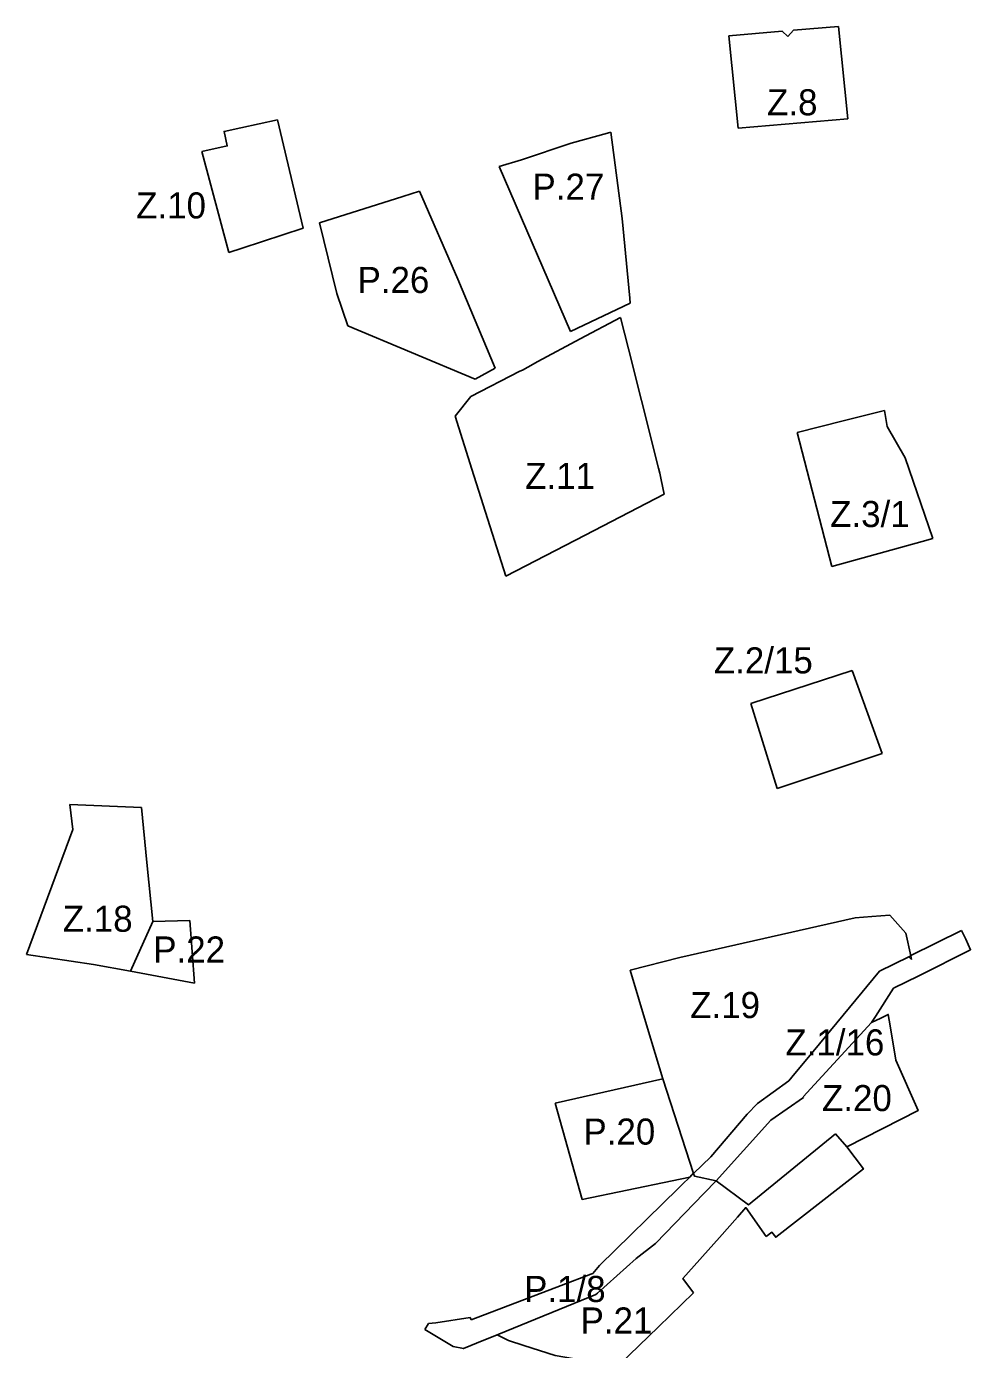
# Model space of a CAD drawing. Extents: x -438701 to -435614, y -1126017 to -1121766.
# Drawn here: x -438217 to -437855, y -1124104 to -1123597 of the extents above; entities that cross this region are included whole.
import ezdxf

# ---------------------------------------------------------------- set-up
doc = ezdxf.new("R2010")
doc.units = 0
for name, color, linetype in [('NAVRH', 7, 'Continuous'), ('STAV', 7, 'Continuous'), ('Vrstva 3', 7, 'Continuous'), ('Vrstva 6', 7, 'Continuous'), ('Vrstva 7', 7, 'Continuous'), ('Vrstva 9', 7, 'Continuous')]:
    doc.layers.add(name, color=color, linetype=linetype)

msp = doc.modelspace()

# ---------------------------------------------------------------- linework, layer by layer
at = {"layer": 'NAVRH'}
for p, q in [((-437905.63, -1123597.23), (-437922.91, -1123598.68)), ((-437902.09, -1123632.64), (-437905.63, -1123597.23)), ((-437927.28, -1123599.05), (-437947.65, -1123600.76)), ((-437947.65, -1123600.76), (-437944.07, -1123636.19)), ((-437925.07, -1123601.06), (-437927.28, -1123599.05)), ((-437922.91, -1123598.68), (-437925.07, -1123601.06)), ((-438110.79, -1123674.54), (-438120.57, -1123632.97)), ((-437944.07, -1123636.19), (-437902.09, -1123632.64)), ((-438149.56, -1123645.16), (-438139.27, -1123683.83)), ((-438024.67, -1123727.86), (-438026.73, -1123728.92)), ((-438020.8, -1123725.67), (-438024.67, -1123727.86)), ((-438046.51, -1123739.05), (-438052.5, -1123746.58)), ((-437887.06, -1123750.53), (-437888.12, -1123744.39)), ((-438052.5, -1123746.58), (-438046.07, -1123766.9)), ((-437921.51, -1123752.84), (-437908.29, -1123804.25)), ((-437880.1, -1123762.54), (-437887.06, -1123750.53)), ((-437869.51, -1123793.43), (-437880.1, -1123762.54)), ((-438046.07, -1123766.9), (-438033.09, -1123807.96)), ((-438002.75, -1123792.21), (-437972.43, -1123776.46)), ((-438033.09, -1123807.96), (-438002.75, -1123792.21)), ((-437908.29, -1123804.25), (-437873.67, -1123794.59)), ((-437873.67, -1123794.59), (-437869.51, -1123793.43)), ((-437900.38, -1123844.04), (-437939.31, -1123856.78)), ((-437889, -1123875.95), (-437900.38, -1123844.04)), ((-437939.31, -1123856.78), (-437929.11, -1123889.32)), ((-437929.11, -1123889.32), (-437889, -1123875.95)), ((-438170.63, -1123917.63), (-438172.73, -1123896.63)), ((-438168.37, -1123940.3), (-438170.63, -1123917.63)), ((-438176.87, -1123959.38), (-438168.37, -1123940.3)), ((-437856.96, -1123947.06), (-437858.53, -1123943.79)), ((-438216.73, -1123952.89), (-438191.04, -1123956.73)), ((-438191.04, -1123956.73), (-438176.87, -1123959.38)), ((-437889.94, -1123959.3), (-437878.74, -1123953.77)), ((-437878.74, -1123953.77), (-437889.94, -1123959.3)), ((-437877.69, -1123954.9), (-437878.74, -1123953.77)), ((-437878.01, -1123953.41), (-437877.69, -1123954.9)), ((-437915.42, -1123990.14), (-437889.94, -1123959.3)), ((-437889.94, -1123959.3), (-437915.42, -1123990.14)), ((-437884.62, -1123965.84), (-437874.86, -1123961.07)), ((-437891.54, -1123976.65), (-437884.62, -1123965.84)), ((-437893.08, -1123979.06), (-437891.54, -1123976.65)), ((-437893.08, -1123979.06), (-437919.27, -1124007.43)), ((-437919.27, -1124007.43), (-437893.08, -1123979.06)), ((-437915.42, -1123990.14), (-437923.54, -1123999.96)), ((-437973, -1124000.58), (-437961.19, -1124036.82)), ((-437924.73, -1124001.41), (-437936.68, -1124010.09)), ((-437923.54, -1123999.96), (-437924.73, -1124001.41)), ((-437919.12, -1124007.7), (-437931.6, -1124016.38)), ((-437931.6, -1124016.38), (-437919.12, -1124007.7)), ((-437919.27, -1124007.43), (-437919.12, -1124007.7)), ((-437919.27, -1124007.43), (-437919.27, -1124007.43)), ((-437919.12, -1124007.7), (-437919.27, -1124007.43)), ((-437936.68, -1124010.09), (-437940.64, -1124014.11)), ((-437954.53, -1124030.45), (-437940.64, -1124014.11)), ((-437940.64, -1124014.11), (-437954.53, -1124030.45)), ((-437931.6, -1124016.38), (-437952.54, -1124039.71)), ((-437952.54, -1124039.71), (-437931.6, -1124016.38)), ((-437961.19, -1124036.82), (-437954.53, -1124030.45)), ((-437954.53, -1124030.45), (-437961.19, -1124036.82))]:
    msp.add_line(p, q, dxfattribs=at)
for points in [[(-438120.57, -1123632.97), (-438134.61, -1123636.07), (-438141.03, -1123637.49), (-438139.81, -1123643.01), (-438149.56, -1123645.16)], [(-438139.27, -1123683.83), (-438134.08, -1123682.17), (-438110.79, -1123674.54)], [(-437989.13, -1123708.74), (-438004.62, -1123717.02), (-438020.8, -1123725.67)], [(-437972.43, -1123776.46), (-437973.64, -1123770.96), (-437974.18, -1123768.47), (-437974.61, -1123766.51), (-437981.12, -1123740.62), (-437986.11, -1123720.75), (-437989.13, -1123708.74)], [(-438026.73, -1123728.92), (-438027.69, -1123729.41), (-438046.51, -1123739.05)], [(-437888.12, -1123744.39), (-437903.91, -1123748.39), (-437921.51, -1123752.84)], [(-438172.73, -1123896.63), (-438200.11, -1123895.5), (-438199.01, -1123905.06), (-438216.73, -1123952.89)], [(-437878.74, -1123953.77), (-437878.01, -1123953.41), (-437879.87, -1123944.81), (-437886.05, -1123937.89), (-437892.87, -1123938.43), (-437899.29, -1123938.94), (-437966.42, -1123954.03), (-437985.43, -1123958.96), (-437978.79, -1123981.19), (-437973, -1124000.58)], [(-437858.53, -1123943.79), (-437877.93, -1123953.37), (-437878.01, -1123953.41)], [(-437874.86, -1123961.07), (-437855.1, -1123951.11), (-437856.96, -1123947.06)], [(-437906.84, -1124021.64), (-437902.45, -1124026.63), (-437875.1, -1124012.7), (-437883.68, -1123993.39), (-437885.91, -1123980.3), (-437886.65, -1123975.93), (-437889.48, -1123977.31), (-437893.08, -1123979.06)], [(-437924.73, -1124001.41), (-437923.54, -1123999.96), (-437915.42, -1123990.14)], [(-437940.64, -1124014.11), (-437936.68, -1124010.09), (-437924.73, -1124001.41)], [(-437952.54, -1124039.71), (-437940.2, -1124048.84), (-437906.84, -1124021.64)], [(-437961.19, -1124036.82), (-437960.85, -1124037.87), (-437952.54, -1124039.71)]]:
    msp.add_lwpolyline(points, dxfattribs=at)
at = {"layer": 'Vrstva 3'}
for p, q in [((-437994.19, -1123638.1), (-438008.04, -1123641.93)), ((-437992.88, -1123637.74), (-437994.19, -1123638.1)), ((-437988.5, -1123670.87), (-437992.88, -1123637.74)), ((-438008.04, -1123641.93), (-438027.17, -1123648.39)), ((-438027.17, -1123648.39), (-438035.64, -1123650.92)), ((-438035.64, -1123650.92), (-438008.28, -1123714.17)), ((-438072.52, -1123662.39), (-438104.43, -1123672.49)), ((-438066.16, -1123660.38), (-438072.52, -1123662.39)), ((-438051.54, -1123694.08), (-438066.16, -1123660.38)), ((-438104.43, -1123672.49), (-438097.86, -1123699.57)), ((-437985.65, -1123701.39), (-437988.5, -1123670.87)), ((-438037.21, -1123728.14), (-438051.54, -1123694.08)), ((-438097.86, -1123699.57), (-438093.58, -1123712)), ((-438008.28, -1123714.17), (-437985.5, -1123703.32)), ((-437985.5, -1123703.32), (-437985.65, -1123701.39)), ((-438093.58, -1123712), (-438044.91, -1123732.46)), ((-438044.91, -1123732.46), (-438037.21, -1123728.14)), ((-438168.37, -1123940.3), (-438176.87, -1123959.38)), ((-438154.2, -1123939.93), (-438168.37, -1123940.3)), ((-438152.43, -1123963.94), (-438154.2, -1123939.93)), ((-438176.87, -1123959.38), (-438152.43, -1123963.94)), ((-437973, -1124000.58), (-438014.16, -1124009.89)), ((-437961.19, -1124036.82), (-437973, -1124000.58)), ((-438014.16, -1124009.89), (-438003.84, -1124046.78)), ((-437902.45, -1124026.63), (-437906.84, -1124021.64)), ((-437962.66, -1124038.25), (-437965.51, -1124041.04)), ((-437962.66, -1124038.25), (-437961.84, -1124037.44)), ((-437961.84, -1124037.44), (-437961.69, -1124037.3)), ((-437961.19, -1124036.82), (-437961.69, -1124037.3)), ((-437961.69, -1124037.3), (-437961.19, -1124036.82)), ((-437966.96, -1124042.46), (-437997.27, -1124072.19)), ((-437965.51, -1124041.04), (-437966.96, -1124042.46)), ((-437957.18, -1124044.39), (-437952.54, -1124039.71)), ((-437952.54, -1124039.71), (-437957.18, -1124044.39)), ((-437975.8, -1124063.77), (-437957.18, -1124044.39)), ((-437957.18, -1124044.39), (-437975.8, -1124063.77)), ((-437983.21, -1124069.45), (-437975.8, -1124063.77)), ((-437975.8, -1124063.77), (-437983.21, -1124069.45)), ((-437997.27, -1124072.19), (-437999.82, -1124075.17)), ((-437983.21, -1124069.45), (-437998.04, -1124082.76)), ((-437999.82, -1124075.17), (-438000.61, -1124075.47)), ((-437998.66, -1124083.31), (-438035.74, -1124098.42)), ((-437998.04, -1124082.76), (-437998.66, -1124083.31)), ((-438062.78, -1124094.35), (-438064.12, -1124096.72)), ((-438059.98, -1124094.12), (-438062.78, -1124094.35)), ((-438046.72, -1124092.12), (-438059.98, -1124094.12)), ((-438046.44, -1124092.99), (-438046.72, -1124092.12)), ((-438064.12, -1124096.72), (-438053.23, -1124103.24)), ((-438036.43, -1124098.7), (-438035.74, -1124098.42)), ((-438035.74, -1124098.42), (-438036.43, -1124098.7)), ((-438036.43, -1124098.7), (-438036.43, -1124098.7)), ((-438036.43, -1124098.7), (-438036.43, -1124098.7))]:
    msp.add_line(p, q, dxfattribs=at)
for points in [[(-437906.84, -1124021.64), (-437940.2, -1124048.84), (-437952.54, -1124039.71)], [(-437933.34, -1124061.06), (-437931.2, -1124059.42), (-437929.73, -1124061.33), (-437896.16, -1124035.09), (-437902.45, -1124026.63)], [(-438003.84, -1124046.78), (-437969.37, -1124039.64), (-437962.66, -1124038.25)], [(-437961.69, -1124037.3), (-437961.84, -1124037.44), (-437962.66, -1124038.25)], [(-437952.54, -1124039.71), (-437960.85, -1124037.87), (-437961.19, -1124036.82)], [(-437961.27, -1124082.58), (-437965.27, -1124077.16), (-437951.29, -1124061.37), (-437944.42, -1124053.61)], [(-437944.42, -1124053.61), (-437941.19, -1124049.96), (-437933.34, -1124061.06)], [(-438035.74, -1124098.42), (-437998.66, -1124083.31), (-437998.04, -1124082.76), (-437983.21, -1124069.45)], [(-438000.61, -1124075.47), (-438011.86, -1124079.77), (-438046.44, -1124092.99)], [(-438036.43, -1124098.7), (-438032.06, -1124100.94), (-438026.23, -1124102.79), (-438014.26, -1124106.6), (-437999.46, -1124109.17), (-437993.22, -1124113.66), (-437974.68, -1124095.62), (-437961.27, -1124082.58)], [(-438053.23, -1124103.24), (-438049.38, -1124103.98), (-438041.56, -1124100.8), (-438040.56, -1124100.39), (-438036.43, -1124098.7)]]:
    msp.add_lwpolyline(points, dxfattribs=at)
at = {"layer": 'Vrstva 6'}
for p, q in [((-437905.63, -1123597.23), (-437922.91, -1123598.68)), ((-437902.09, -1123632.64), (-437905.63, -1123597.23)), ((-437927.28, -1123599.05), (-437947.65, -1123600.76)), ((-437947.65, -1123600.76), (-437944.07, -1123636.19)), ((-437925.07, -1123601.06), (-437927.28, -1123599.05)), ((-437922.91, -1123598.68), (-437925.07, -1123601.06)), ((-438110.79, -1123674.54), (-438120.57, -1123632.97)), ((-437944.07, -1123636.19), (-437902.09, -1123632.64)), ((-438149.56, -1123645.16), (-438139.27, -1123683.83)), ((-438024.67, -1123727.86), (-438026.73, -1123728.92)), ((-438020.8, -1123725.67), (-438024.67, -1123727.86)), ((-438046.51, -1123739.05), (-438052.5, -1123746.58)), ((-437887.06, -1123750.53), (-437888.12, -1123744.39)), ((-438052.5, -1123746.58), (-438046.07, -1123766.9)), ((-437921.51, -1123752.84), (-437908.29, -1123804.25)), ((-437880.1, -1123762.54), (-437887.06, -1123750.53)), ((-437869.51, -1123793.43), (-437880.1, -1123762.54)), ((-438046.07, -1123766.9), (-438033.09, -1123807.96)), ((-438002.75, -1123792.21), (-437972.43, -1123776.46)), ((-438033.09, -1123807.96), (-438002.75, -1123792.21)), ((-437908.29, -1123804.25), (-437873.67, -1123794.59)), ((-437873.67, -1123794.59), (-437869.51, -1123793.43)), ((-437900.38, -1123844.04), (-437939.31, -1123856.78)), ((-437889, -1123875.95), (-437900.38, -1123844.04)), ((-437939.31, -1123856.78), (-437929.11, -1123889.32)), ((-437929.11, -1123889.32), (-437889, -1123875.95)), ((-438170.63, -1123917.63), (-438172.73, -1123896.63)), ((-438168.37, -1123940.3), (-438170.63, -1123917.63)), ((-438176.87, -1123959.38), (-438168.37, -1123940.3)), ((-437856.96, -1123947.06), (-437858.53, -1123943.79)), ((-438216.73, -1123952.89), (-438191.04, -1123956.73)), ((-438191.04, -1123956.73), (-438176.87, -1123959.38)), ((-437889.94, -1123959.3), (-437878.74, -1123953.77)), ((-437878.74, -1123953.77), (-437889.94, -1123959.3)), ((-437877.69, -1123954.9), (-437878.74, -1123953.77)), ((-437878.01, -1123953.41), (-437877.69, -1123954.9)), ((-437915.42, -1123990.14), (-437889.94, -1123959.3)), ((-437889.94, -1123959.3), (-437915.42, -1123990.14)), ((-437884.62, -1123965.84), (-437874.86, -1123961.07)), ((-437891.54, -1123976.65), (-437884.62, -1123965.84)), ((-437893.08, -1123979.06), (-437891.54, -1123976.65)), ((-437919.27, -1124007.43), (-437893.08, -1123979.06)), ((-437893.08, -1123979.06), (-437919.27, -1124007.43)), ((-437915.42, -1123990.14), (-437923.54, -1123999.96)), ((-437973, -1124000.58), (-437961.19, -1124036.82)), ((-437936.68, -1124010.09), (-437924.73, -1124001.41)), ((-437924.73, -1124001.41), (-437936.68, -1124010.09)), ((-437923.54, -1123999.96), (-437924.73, -1124001.41)), ((-437931.6, -1124016.38), (-437919.12, -1124007.7)), ((-437919.12, -1124007.7), (-437931.6, -1124016.38)), ((-437919.12, -1124007.7), (-437919.27, -1124007.43)), ((-437919.27, -1124007.43), (-437919.12, -1124007.7)), ((-437940.64, -1124014.11), (-437936.68, -1124010.09)), ((-437936.68, -1124010.09), (-437940.64, -1124014.11)), ((-437954.53, -1124030.45), (-437940.64, -1124014.11)), ((-437940.64, -1124014.11), (-437954.53, -1124030.45)), ((-437952.54, -1124039.71), (-437931.6, -1124016.38)), ((-437931.6, -1124016.38), (-437952.54, -1124039.71)), ((-437961.19, -1124036.82), (-437954.53, -1124030.45)), ((-437954.53, -1124030.45), (-437961.19, -1124036.82))]:
    msp.add_line(p, q, dxfattribs=at)
for points in [[(-438120.57, -1123632.97), (-438134.61, -1123636.07), (-438141.03, -1123637.49), (-438139.81, -1123643.01), (-438149.56, -1123645.16)], [(-438139.27, -1123683.83), (-438134.08, -1123682.17), (-438110.79, -1123674.54)], [(-437989.13, -1123708.74), (-438004.62, -1123717.02), (-438020.8, -1123725.67)], [(-437972.43, -1123776.46), (-437973.64, -1123770.96), (-437974.18, -1123768.47), (-437974.61, -1123766.51), (-437981.12, -1123740.62), (-437986.11, -1123720.75), (-437989.13, -1123708.74)], [(-438026.73, -1123728.92), (-438027.69, -1123729.41), (-438046.51, -1123739.05)], [(-437888.12, -1123744.39), (-437903.91, -1123748.39), (-437921.51, -1123752.84)], [(-438172.73, -1123896.63), (-438200.11, -1123895.5), (-438199.01, -1123905.06), (-438216.73, -1123952.89)], [(-437878.74, -1123953.77), (-437878.01, -1123953.41), (-437879.87, -1123944.81), (-437886.05, -1123937.89), (-437892.87, -1123938.43), (-437899.29, -1123938.94), (-437966.42, -1123954.03), (-437985.43, -1123958.96), (-437978.79, -1123981.19), (-437973, -1124000.58)], [(-437858.53, -1123943.79), (-437877.93, -1123953.37), (-437878.01, -1123953.41)], [(-437874.86, -1123961.07), (-437855.1, -1123951.11), (-437856.96, -1123947.06)], [(-437906.84, -1124021.64), (-437902.45, -1124026.63), (-437875.1, -1124012.7), (-437883.68, -1123993.39), (-437885.91, -1123980.3), (-437886.65, -1123975.93), (-437889.48, -1123977.31), (-437893.08, -1123979.06)], [(-437924.73, -1124001.41), (-437923.54, -1123999.96), (-437915.42, -1123990.14)], [(-437952.54, -1124039.71), (-437940.2, -1124048.84), (-437906.84, -1124021.64)], [(-437961.19, -1124036.82), (-437960.85, -1124037.87), (-437952.54, -1124039.71)]]:
    msp.add_lwpolyline(points, dxfattribs=at)
at = {"layer": 'Vrstva 7'}
for p, q in [((-437994.19, -1123638.1), (-438008.04, -1123641.93)), ((-437992.88, -1123637.74), (-437994.19, -1123638.1)), ((-437988.5, -1123670.87), (-437992.88, -1123637.74)), ((-438008.04, -1123641.93), (-438027.17, -1123648.39)), ((-438027.17, -1123648.39), (-438035.64, -1123650.92)), ((-438035.64, -1123650.92), (-438008.28, -1123714.17)), ((-438072.52, -1123662.39), (-438104.43, -1123672.49)), ((-438066.16, -1123660.38), (-438072.52, -1123662.39)), ((-438051.54, -1123694.08), (-438066.16, -1123660.38)), ((-438104.43, -1123672.49), (-438097.86, -1123699.57)), ((-437985.65, -1123701.39), (-437988.5, -1123670.87)), ((-438037.21, -1123728.14), (-438051.54, -1123694.08)), ((-438097.86, -1123699.57), (-438093.58, -1123712)), ((-438008.28, -1123714.17), (-437985.5, -1123703.32)), ((-437985.5, -1123703.32), (-437985.65, -1123701.39)), ((-438093.58, -1123712), (-438044.91, -1123732.46)), ((-438044.91, -1123732.46), (-438037.21, -1123728.14)), ((-438168.37, -1123940.3), (-438176.87, -1123959.38)), ((-438154.2, -1123939.93), (-438168.37, -1123940.3)), ((-438152.43, -1123963.94), (-438154.2, -1123939.93)), ((-438176.87, -1123959.38), (-438152.43, -1123963.94)), ((-437973, -1124000.58), (-438014.16, -1124009.89)), ((-437961.19, -1124036.82), (-437973, -1124000.58)), ((-438014.16, -1124009.89), (-438003.84, -1124046.78)), ((-437902.45, -1124026.63), (-437906.84, -1124021.64)), ((-437962.66, -1124038.25), (-437965.51, -1124041.04)), ((-437962.66, -1124038.25), (-437961.84, -1124037.44)), ((-437961.84, -1124037.44), (-437961.69, -1124037.3)), ((-437961.19, -1124036.82), (-437961.69, -1124037.3)), ((-437961.69, -1124037.3), (-437961.19, -1124036.82)), ((-437966.96, -1124042.46), (-437997.27, -1124072.19)), ((-437965.51, -1124041.04), (-437966.96, -1124042.46)), ((-437957.18, -1124044.39), (-437952.54, -1124039.71)), ((-437952.54, -1124039.71), (-437957.18, -1124044.39)), ((-437975.8, -1124063.77), (-437957.18, -1124044.39)), ((-437957.18, -1124044.39), (-437975.8, -1124063.77)), ((-437983.21, -1124069.45), (-437975.8, -1124063.77)), ((-437975.8, -1124063.77), (-437983.21, -1124069.45)), ((-437997.27, -1124072.19), (-437999.82, -1124075.17)), ((-437983.21, -1124069.45), (-437998.04, -1124082.76)), ((-437999.82, -1124075.17), (-438000.61, -1124075.47)), ((-437998.66, -1124083.31), (-438035.74, -1124098.42)), ((-437998.04, -1124082.76), (-437998.66, -1124083.31)), ((-438062.78, -1124094.35), (-438064.12, -1124096.72)), ((-438059.98, -1124094.12), (-438062.78, -1124094.35)), ((-438046.72, -1124092.12), (-438059.98, -1124094.12)), ((-438046.44, -1124092.99), (-438046.72, -1124092.12)), ((-438064.12, -1124096.72), (-438053.23, -1124103.24)), ((-438036.43, -1124098.7), (-438035.74, -1124098.42)), ((-438035.74, -1124098.42), (-438036.43, -1124098.7))]:
    msp.add_line(p, q, dxfattribs=at)
for points in [[(-437906.84, -1124021.64), (-437940.2, -1124048.84), (-437952.54, -1124039.71)], [(-437933.34, -1124061.06), (-437931.2, -1124059.42), (-437929.73, -1124061.33), (-437896.16, -1124035.09), (-437902.45, -1124026.63)], [(-438003.84, -1124046.78), (-437969.37, -1124039.64), (-437962.66, -1124038.25)], [(-437961.69, -1124037.3), (-437961.84, -1124037.44), (-437962.66, -1124038.25)], [(-437952.54, -1124039.71), (-437960.85, -1124037.87), (-437961.19, -1124036.82)], [(-437961.27, -1124082.58), (-437965.27, -1124077.16), (-437951.29, -1124061.37), (-437944.42, -1124053.61)], [(-437944.42, -1124053.61), (-437941.19, -1124049.96), (-437933.34, -1124061.06)], [(-438035.74, -1124098.42), (-437998.66, -1124083.31), (-437998.04, -1124082.76), (-437983.21, -1124069.45)], [(-438000.61, -1124075.47), (-438011.86, -1124079.77), (-438046.44, -1124092.99)], [(-438036.43, -1124098.7), (-438032.06, -1124100.94), (-438026.23, -1124102.79), (-438014.26, -1124106.6), (-437999.46, -1124109.17), (-437993.22, -1124113.66), (-437974.68, -1124095.62), (-437961.27, -1124082.58)], [(-438053.23, -1124103.24), (-438049.38, -1124103.98), (-438041.56, -1124100.8), (-438040.56, -1124100.39), (-438036.43, -1124098.7)]]:
    msp.add_lwpolyline(points, dxfattribs=at)

# ---------------------------------------------------------------- texts
at = {"layer": 'STAV'}
for s, p in [('P.27', (-438022.91, -1123663.65)), ('P.26', (-438089.91, -1123699.38)), ('P.22', (-438168.17, -1123956.02)), ('P.20', (-438003.39, -1124025.81)), ('P.1/8', (-438026.1, -1124086.13)), ('P.21', (-438004.47, -1124098.22))]:
    msp.add_text(s, height=10, dxfattribs=at).set_placement(p)
at = {"layer": 'Vrstva 9'}
for s, p in [('Z.8', (-437933.05, -1123631.29)), ('Z.10', (-438174.73, -1123670.82)), ('Z.11', (-438025.72, -1123774.49)), ('Z.3/1', (-437908.89, -1123789.1)), ('Z.2/15', (-437953.43, -1123845.2)), ('Z.18', (-438202.83, -1123944.23)), ('Z.19', (-437962.5, -1123977.3)), ('Z.1/16', (-437926.02, -1123991.62)), ('Z.20', (-437912, -1124012.97))]:
    msp.add_text(s, height=10, dxfattribs=at).set_placement(p)

doc.saveas('drawing.dxf')
